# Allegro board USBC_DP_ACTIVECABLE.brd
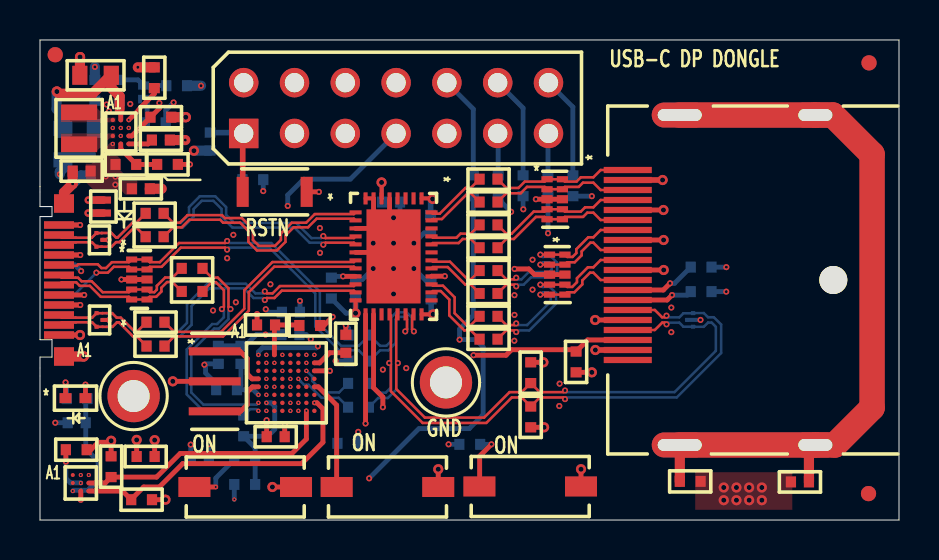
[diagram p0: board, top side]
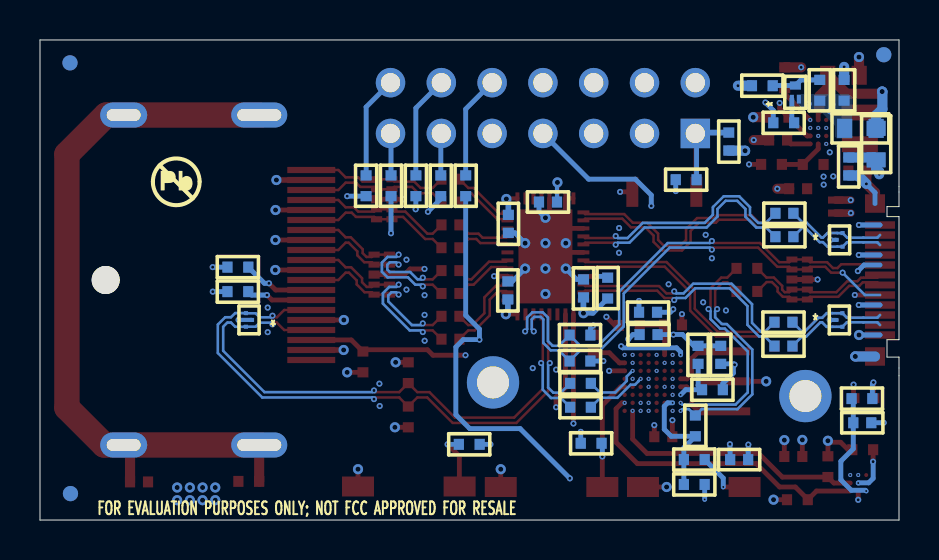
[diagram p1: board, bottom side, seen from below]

Outline 42.95 x 24 mm; copper layers: TOP, L2_GND, L3_SIG, L4_3P3V, L5_GND, BOTTOM. Coordinates in mm from the lower left corner of the outline.
Outline path: 0,24 0,15.67 0.6,15.67 0.6,15.17 0,15.17 0,9.02 0.6,9.02 0.6,8.15 0,8.15 0,0 42.95,0 42.95,24 0,24

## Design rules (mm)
net group DIFFPAIR0: nets DP_ML0N_ML3P DP_ML0P_ML3N
net group DIFFPAIR1: nets DP_ML1N_ML2P DP_ML1P_ML2N
net group DIFFPAIR2: nets DP_ML2N_ML1P DP_ML2P_ML1N
net group DIFFPAIR3: nets DP_ML3N_ML0P DP_ML3P_ML0N
net group DIFFPAIR4: nets N17413185 N17413188
net group DIFFPAIR5: nets N17413191 N17413194
net group DIFFPAIR6: nets N17413197 N17413200
net group DIFFPAIR7: nets N17413203 N17413206
net group DIFFPAIR8: nets DP_AUXN DP_AUXP
net group DIFFPAIR9: nets A10_RX2N_ML0N_ML3P A11_RX2P_ML0P_ML3N
net group DIFFPAIR10: nets N17415406 N17415415
net group DIFFPAIR11: nets A2_TX1P_ML2P_ML1N A3_TX1N_ML2N_ML1P
net group DIFFPAIR12: nets N17415496 N17415505
net group DIFFPAIR13: nets DM_USBC DP_USBC
net group DIFFPAIR14: nets B10_RX1N_ML3N_ML0P B11_RX1P_ML3P_ML0N
net group DIFFPAIR15: nets N17415457 N17415476
net group DIFFPAIR16: nets B2_TX2P_ML1P_ML2N B3_TX2N_ML1N_ML2P
net group DIFFPAIR17: nets N17415424 N17415436
net group DIFFPAIR18: nets USBC_SBU1_AUXP USBC_SBU2_AUXN
net group DIFFPAIR19: nets MSP_DPAUXN MSP_DPAUXP
net group DIFFPAIR20: nets DM_USBC_R DP_USBC_R

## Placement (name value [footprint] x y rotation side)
C1  220nF  [C0402]  5.78 8.7 180 top
C2  220nF  [C0402]  5.78 9.89 180 top
C3  100nF  [C0402]  19.56 11.48 270 bottom
C4  100nF  [C0402]  15.77 11.58 270 bottom
C5  220nF  [C0402]  22.43 17.04 180 top
C6  220nF  [C0402]  5.78 9.89 180 bottom
C7  220nF  [C0402]  22.43 15.9 180 top
C8  220nF  [C0402]  5.78 8.7 180 bottom
C9  220nF  [C0402]  22.43 14.76 180 top
C10  220nF  [C0402]  22.43 13.61 180 top
C11  220nF  [C0402]  22.43 12.47 180 top
C12  220pF  [C0402]  1.84 4.86 0 bottom
C13  220nF  [C0402]  5.73 14.17 180 bottom
C14  220nF  [C0402]  22.43 10.19 180 top
C15  220nF  [C0402]  22.43 11.33 180 top
C16  220nF  [C0402]  5.73 15.34 180 bottom
C17  4.7uF  [C0402]  2.51 17.68 270 bottom
C18  220nF  [C0402]  22.43 9.04 180 top
C19  1uF  [C0402]  38 1.91 180 top
C20  220nF  [C0402]  5.73 14.17 180 top
C21  220nF  [C0402]  5.73 15.33 180 top
C22  100nF  [C0402]  19.53 14.81 90 bottom
C23  100nF  [C0402]  17.55 15.9 180 bottom
C24  100nF  [C0402]  5.28 3.17 180 top
C25  220nF  [C0402]  7.99 3.02 180 bottom
C26  220nF  [C0402]  10.05 8.26 90 bottom
C27  1uF  [C0402]  8.92 8.26 90 bottom
C28  1nF  [C0402]  8.51 18.92 270 bottom
C29  100nF  [C0402]  11.79 4.17 180 top
C30  1uF  [C0402]  12.52 9.27 180 bottom
C31  100nF  [C0402]  12.55 10.39 180 bottom
C32  100nF  [C0402]  11.3 9.75 180 top
C33  470nF  [C0402]  15.29 8.81 90 top
C34  10uF  [C0603]  2.78 22.24 180 top
C35  10uF  [C0402]  5.04 16.57 0 top
C36  10uF  [C0402]  2.08 17.45 180 top
C37  1nF  [C0402]  6.05 19 180 top
D1  TPD1E05U06  [DPY0002AA]  1.78 6.09 0 top
D2  ESD114-U1-02EL  [SOD_882]  3.17 15.67 90 top
J1  Display_Port_Connector_Source  [CON_DP_SD-47272-001]  39.67 12 90 top
J2  DNI,HEADER 7X2  [HDR_THVT_2X7_100_M]  10.19 19.33 90 top
L1  1.5uH  [IND_DFE2016C]  1.96 19.58 270 top
LP1  DNI,LP_RED  [TP_THVT_060_RND]  4.68 6.2 0 top
LP2  DNI,LP_BLACK  [TP_THVT_060_RND]  20.3 6.88 0 top
NOREF  -  []  0 23.79 0 top
NOREF#2  -  []  42.72 0 90 top
NOREF#3  -  []  88.9 38.1 0 top
NOREF#4  -  []  -3.81 -69.85 0 top
NOREF#5  -  [unnamed#2]  41.43 1.32 0 top
NOREF#6  -  [unnamed#2]  0.76 23.27 0 top
NOREF#7  -  [unnamed#2]  41.45 22.86 0 top
NOREF#8  -  []  0 0 0 top
NOREF#9  -  [unnamed#2]  0.76 23.27 180 bottom
NOREF#10  -  []  36.11 16.94 180 bottom
NOREF#11  -  [unnamed#2]  41.45 22.86 180 bottom
NOREF#12  -  []  40.88 3.71 180 bottom
NOREF#13  -  [unnamed#2]  41.43 1.32 180 bottom
P1  Wurth 632712000021  [USB-C_SMRT_632_712_000_021]  0 12 90 top
Q1  TF412S  [SOT-883]  5.18 21.39 90 bottom
R1  1k  [R0402]  14.57 11.6 270 bottom
R2  0  [R0402]  1.85 6.07 180 bottom
R3  1M  [R0402]  32.51 1.93 0 top
R4  1M  [R0402]  26.8 7.9 270 top
R5  1M  [R0402]  33.06 12.64 0 bottom
R6  1M  [R0402]  33.06 11.42 0 bottom
R7  0  [R0402]  15.93 6.83 0 bottom
R8  0  [R0402]  15.93 5.64 0 bottom
R9  2M  [R0402]  15.95 7.95 180 bottom
R10  2M  [R0402]  15.95 9.25 180 bottom
R11  4.7M  [R0402]  24.54 7.37 90 top
R12  470k  [R0402]  24.54 5.16 270 top
R13  100k  [R0402]  3.96 21.49 90 bottom
R14  0  [R0402]  6.83 21.72 180 bottom
R15  806  [R0402]  5.77 19.86 0 bottom
R16  DNI,1k  [R0402]  2.74 21.49 90 bottom
R17  4.7k  [R0402]  5.08 1.02 180 top
R18  4.7k  [R0402]  3.56 2.67 270 top
R19  100k  [R0402]  1.81 3.52 180 top
R20  47k  [R0402]  10.64 17.02 180 bottom
R21  1.4k  [R0402]  10.18 4.71 90 bottom
R22  100  [R0402]  10.24 3.02 0 bottom
R23  1M  [R0402]  10.24 1.78 0 bottom
R24  0  [R0402]  9.33 6.52 0 bottom
R25  0  [R0402]  13.49 9.73 0 top
R26  0  [R0402]  26.64 16.71 270 bottom
R27  0  [R0402]  24.16 16.71 270 bottom
R28  DNI,0  [R0402]  22.91 16.71 270 bottom
R29  DNI,0  [R0402]  25.4 16.71 270 bottom
R30  DNI,100k  [R0402]  15.39 3.84 180 bottom
R31  DNI,100k  [R0402]  21.49 3.78 0 bottom
R32  DNI,0  [R0402]  21.67 16.71 90 bottom
R33  DNI,0  [R0603]  1.14 18.8 90 bottom
R34  0  [R0603]  1.93 19.58 180 bottom
R35  0  [R0402]  4.29 17.78 180 top
R36  1M  [R0402]  6.05 20.14 180 top
R37  DNI,100k  [R0402]  6.38 17.78 180 top
R38  100k  [R0402]  5.71 22.12 270 top
R39  27  [R0402]  7.6 12.58 0 top
R40  27  [R0402]  7.6 11.43 0 top
SW1  DIP_SPST  [SW_SMVT_CHS-01TA]  10.26 1.65 0 top
SW2  PushButton-SPST  [SW_SMVT_KXT]  11.73 16.41 180 top
SW3  DIP_SPST  [SW_SMVT_CHS-01TA]  17.37 1.65 0 top
SW4  DIP_SPST  [SW_SMVT_CHS-01TA]  24.51 1.68 0 top
U1  TUSB544  [RNQ0040A]  17.68 13.18 270 top
U2  TPD4E05U06  [DQA0010A]  4.97 12.03 0 top
U3  TUSB422IYFP  [YFP_BGA_9]  2.04 1.85 0 top
U4  MSP430F5528IYFF  [YFF0064A]  12.32 6.86 0 top
U5  TPS63051YFFT  [YFF0012A]  4.04 19.41 0 top
U6  TPD4E02B04  [DQA]  25.74 16.04 270 top
U7  TPD4E02B04  [DQA]  25.86 12.27 270 top
U8  ESD122  [DMX0003A]  2.97 14.01 180 top
U9  ESD122  [DMX0003A]  2.97 14.01 180 bottom
U10  ESD122  [DMX0003A]  2.98 10 180 bottom
U11  ESD122  [DMX0003A]  2.98 10 180 top
U12  ESD122  [DMX0003A]  32.5 10.01 0 bottom
Y1  4MHz  [XTAL_SM_3_CSTCR_G15L]  8.74 6.93 270 top

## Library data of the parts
C1 C2 C5-C16 C18 C20 C21 C37 = cc0402
C3 C4 C22-C24 = CAP NP
C17 C19 C25-C36 = CAP
D1 D2 = TPD1E05U06
J1 = Display_Port_Connector_Source_0
J2 = HEADER 7X2
L1 = INDUCTOR
LP1 LP2 = TESTLOOP
P1 = Type C Plug_0
Q1 = TF412S
R1 R2 R7 R8 R13-R16 R33-R35 R37 R38 = R
R3-R6 R9-R12 R17-R32 R36 R39 R40 = R_2
SW1-SW4 = SW MAG-SPST
U1 = TUSB1044RNQ
U2 = TPD4E05U06
U3 = TUSB422_WCSP
U4 = MSP430F5528IYFF_1
U5 = TPS63051YFFT
U6 U7 = TPD4E02B04
U8-U12 = ESD122
Y1 = XM/SM_0

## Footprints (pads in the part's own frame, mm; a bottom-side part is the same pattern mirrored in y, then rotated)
C0402
  rect 0.51x0.55 smd: 1(-0.45,0) 2(0.45,0)
C0603
  rect 0.76x0.95 smd: 1(-0.787,0) 2(0.787,0)
CON_DP_SD-47272-001
  round 1.4 hole 1.4 unplated: (0,0)
  rect 0.31x2.4 smd: 1(5.5,10.28) 2(5,10.28) 3(4.5,10.28) 4(4,10.28) 5(3.5,10.28) 6(3,10.28) 7(2.5,10.28) 8(2,10.28) 9(1.5,10.28) 10(1,10.28) 11(0.5,10.28) 12(0,10.28) 13(-0.5,10.28) 14(-1,10.28) 15(-1.5,10.28) 16(-2,10.28) 17(-2.5,10.28) 18(-3,10.28) 19(-3.5,10.28) 20(-4,10.28)
  oval 1.25x2.8 hole 0.6x2.2: 21(-8.25,7.68) 24(8.25,7.68)
  oval 1.25x2.35 hole 0.6x1.7: 22(-8.25,0.9) 23(8.25,0.9)
DMX0003A
  rect 0.2x0.2 smd: 1(-0.15,0) 2(0.15,-0.34) 3(0.15,0.34)
DPY0002AA
  rect 0.6x0.5 smd: 1(-0.5,0) 2(0.5,0)
DQA
  rect 0.305x0.559 smd: 1(-1,-0.385) 2(-0.5,-0.385) 4(0.5,-0.385) 5(1,-0.385) 6(1,0.385) 7(0.5,0.385) 9(-0.5,0.385) 10(-1,0.385)
  rect 0.406x0.559 smd: 3(0,-0.385) 8(0,0.385)
DQA0010A
  rect 0.55x0.3 smd: 1(-0.385,1) 2(-0.385,0.5) 4(-0.385,-0.5) 5(-0.385,-1) 6(0.385,-1) 7(0.385,-0.5) 9(0.385,0.5) 10(0.385,1)
  rect 0.55x0.4 smd: 3(-0.385,0) 8(0.385,0)
HDR_THVT_2X7_100_M
  rect 1.473x1.473 hole 0.965: 1(0,0)
  round 1.473 hole 0.965: 2(2.54,0) 3(0,-2.54) 4(2.54,-2.54) 5(0,-5.08) 6(2.54,-5.08) 7(0,-7.62) 8(2.54,-7.62) 9(0,-10.16) 10(2.54,-10.16) 11(0,-12.7) 12(2.54,-12.7) 13(0,-15.24) 14(2.54,-15.24)
IND_DFE2016C
  rect 0.787x1.803 smd: 1(-0.794,0) 2(0.794,0)
R0402
  rect 0.51x0.55 smd: 1(-0.52,0) 2(0.52,0)
R0603
  rect 0.76x0.95 smd: 1(-0.787,0) 2(0.787,0)
RNQ0040A
  rect 0.6x0.2 smd: 1(-2.9,1.4) 2(-2.9,1) 3(-2.9,0.6) 4(-2.9,0.2) 5(-2.9,-0.2) 6(-2.9,-0.6) 7(-2.9,-1) 8(-2.9,-1.4) 21(2.9,-1.4) 22(2.9,-1) 23(2.9,-0.6) 24(2.9,-0.2) 25(2.9,0.2) 26(2.9,0.6) 27(2.9,1) 28(2.9,1.4)
  rect 0.2x0.6 smd: 9(-2.2,-1.9) 10(-1.8,-1.9) 11(-1.4,-1.9) 12(-1,-1.9) 13(-0.6,-1.9) 14(-0.2,-1.9) 15(0.2,-1.9) 16(0.6,-1.9) 17(1,-1.9) 18(1.4,-1.9) 19(1.8,-1.9) 20(2.2,-1.9) 29(2.2,1.9) 30(1.8,1.9) 31(1.4,1.9) 32(1,1.9) 33(0.6,1.9) 34(0.2,1.9) 35(-0.2,1.9) 36(-0.6,1.9) 37(-1,1.9) 38(-1.4,1.9) 39(-1.8,1.9) 40(-2.2,1.9)
  rect 4.7x2.7 smd: 41(0,0)
SOD_882
  rect 0.356x0.762 smd: 1(-0.325,0) 2(0.325,0)
SOT-883
  rect 0.43x0.2 smd: 1(-0.34,0.175) 2(-0.34,-0.175)
  rect 0.41x0.55 smd: 3(0.34,0)
SW_SMVT_CHS-01TA
  rect 1.6x1 smd: 1(-2.54,0) 2(2.54,0)
SW_SMVT_KXT
  rect 0.6x1.5 smd: 1(-1.6,0) 2(1.6,0)
TP_THVT_060_RND
  round 2.616 hole 1.6: 1(0,0)
unnamed#2
  round 0.762 smd: (0,0)
USB-C_SMRT_632_712_000_021
  rect 0.35x1.5 smd: A1(-2.75,-0.95) A2(-2.25,-0.95) A3(-1.75,-0.95) A4(-1.25,-0.95) A5(-0.75,-0.95) A6(-0.25,-0.95) A7(0.25,-0.95) A8(0.75,-0.95) A9(1.25,-0.95) A10(1.75,-0.95) A11(2.25,-0.95) A12(2.75,-0.95) B1(2.75,-0.95) B2(2.25,-0.95) B3(1.75,-0.95) B4(1.25,-0.95) B5(0.75,-0.95) B8(-0.75,-0.95) B9(-1.25,-0.95) B10(-1.75,-0.95) B11(-2.25,-0.95) B12(-2.75,-0.95)
  rect 0.9x1 smd: C1(-3.825,-1.2) C2(3.825,-1.2) C3(-3.825,-1.2) C4(3.825,-1.2)
XTAL_SM_3_CSTCR_G15L
  rect 0.4x2.6 smd: 1(-1.5,0) 2(0,0) 3(1.5,0)
YFF0012A
  round 0.22 smd: A1(-0.4,0.6) A2(0,0.6) A3(0.4,0.6) B1(-0.4,0.2) B2(0,0.2) B3(0.4,0.2) C1(-0.4,-0.2) C2(0,-0.2) C3(0.4,-0.2) D1(-0.4,-0.6) D2(0,-0.6) D3(0.4,-0.6)
YFF0064A
  round 0.22 smd: A1(-1.4,1.4) A2(-1,1.4) A3(-0.6,1.4) A4(-0.2,1.4) A5(0.2,1.4) A6(0.6,1.4) A7(1,1.4) A8(1.4,1.4) B1(-1.4,1) B2(-1,1) B3(-0.6,1) B4(-0.2,1) B5(0.2,1) B6(0.6,1) B7(1,1) B8(1.4,1) C1(-1.4,0.6) C2(-1,0.6) C3(-0.6,0.6) C4(-0.2,0.6) C5(0.2,0.6) C6(0.6,0.6) C7(1,0.6) C8(1.4,0.6) D1(-1.4,0.2) D2(-1,0.2) D3(-0.6,0.2) D4(-0.2,0.2) D5(0.2,0.2) D6(0.6,0.2) D7(1,0.2) D8(1.4,0.2) E1(-1.4,-0.2) E2(-1,-0.2) E3(-0.6,-0.2) E4(-0.2,-0.2) E5(0.2,-0.2) E6(0.6,-0.2) E7(1,-0.2) E8(1.4,-0.2) F1(-1.4,-0.6) F2(-1,-0.6) F3(-0.6,-0.6) F4(-0.2,-0.6) F5(0.2,-0.6) F6(0.6,-0.6) F7(1,-0.6) F8(1.4,-0.6) G1(-1.4,-1) G2(-1,-1) G3(-0.6,-1) G4(-0.2,-1) G5(0.2,-1) G6(0.6,-1) G7(1,-1) G8(1.4,-1) H1(-1.4,-1.4) H2(-1,-1.4) H3(-0.6,-1.4) H4(-0.2,-1.4) H5(0.2,-1.4) H6(0.6,-1.4) H7(1,-1.4) H8(1.4,-1.4)
YFP_BGA_9
  round 0.2 smd: A1(-0.4,0.4) A2(0,0.4) A3(0.4,0.4) B1(-0.4,0) B2(0,0) B3(0.4,0) C1(-0.4,-0.4) C2(0,-0.4) C3(0.4,-0.4)

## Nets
GND: C3.1 C4.1 C12.1 C17.2(B) C19.2(B) C22.1 C23.1 C24.1 C25.2(B) C26.2(B) C27.2(B) C28.2(B) C29.2(B) C30.2(B) C31.2(B) C32.2(B) C33.2(B) C34.2(B) C35.2(B) C36.2(B) C37.1 D1.2(A) D2.2(A) J1.2(GND1) J1.5(GND2) J1.8(GND3) J1.11(GND4) J1.16(GND6) J1.19(RTN) J2.9 LP2.1 P1.A1(GND#A1) P1.A12(GND#A12) P1.B1(GND#B1) P1.B12(GND#B12) P1.C1(GND#C1) P1.C2(GND#C2) P1.C3(GND#C3) P1.C4(GND#C4) R3.2 R4.2 R5.2 R6.2 R9.2 R10.2 R11.2 R12.2 R15.2 R16.2 R23.1 R37.1 R38.1 SW2.1 SW3.2 SW4.2 U1.5(SWAP) U1.7(SLP_S0#) U1.8(DIR0) U1.11(DIR1) U1.14(VIO_SEL) U1.41(PAD/GND) U2.3(GND#3) U2.8(GND#8) U3.C2(GND) U4.A4(AVSS1) U4.A8(DVSS1) U4.D2(AVSS2) U4.H2(VSSU) U4.H6(DVSS2) U5.B1(GND) U5.C2(PFM/PWM) U6.3(GND#3) U6.8(GND#8) U7.3(GND#3) U7.8(GND#8) U8.1(GND) U9.1(GND) U10.1(GND) U11.1(GND) U12.1(GND) Y1.2(GND)
A2_TX1P_ML2P_ML1N: C1.2 P1.A2(SSTXP1) U11.3(IO2)
A3_TX1N_ML2N_ML1P: C2.2 P1.A3(SSTXN1) U11.2(IO1)
A10_RX2N_ML0N_ML3P: C20.2 P1.A10(SSRXN2) U8.3(IO2)
A11_RX2P_ML0P_ML3N: C21.2 P1.A11(SSRXP2) U8.2(IO1)
B2_TX2P_ML1P_ML2N: C16.2 P1.B2(SSTXP2) U9.3(IO2)
B3_TX2N_ML1N_ML2P: C13.2 P1.B3(SSTXN2) U9.2(IO1)
B10_RX1N_ML3N_ML0P: C6.2 P1.B10(SSRXN1) U10.3(IO2)
B11_RX1P_ML3P_ML0N: C8.2 P1.B11(SSRXP1) U10.2(IO1)
C_CC1: C12.2 R2.1 U3.C1(CC1)
DM_USBC: P1.A7(DN1) R39.1 U2.4(D2+) U2.7(NC7)
DM_USBC_R: R39.2 U4.G1(PU.1/DM)
DP_AUXN: J1.17(AUX_N) R8.2 R11.1 U1.25(AUXN) U12.3(IO2)
DP_AUXP: J1.15(AUX_P) R7.2 R12.1 U1.24(AUXP) U12.2(IO1)
DP_CAD: J1.13(CAD) R5.1
DP_ML0N_ML3P: C7.1 J1.3(ML_0N) U6.2(IO2) U6.9(NC9)
DP_ML0P_ML3N: C5.1 J1.1(ML_0P) U6.1(IO1) U6.10(NC10)
DP_ML1N_ML2P: C10.1 J1.6(ML_1N) U6.5(IO4) U6.6(NC6)
DP_ML1P_ML2N: C9.1 J1.4(ML_1P) U6.4(IO3) U6.7(NC7)
DP_ML2N_ML1P: C11.1 J1.9(ML_2N) U7.2(IO2) U7.9(NC9)
DP_ML2P_ML1N: C15.1 J1.7(ML_2P) U7.1(IO1) U7.10(NC10)
DP_ML3N_ML0P: C14.1 J1.12(ML_3N) U7.5(IO4) U7.6(NC6)
DP_ML3P_ML0N: C18.1 J1.10(ML_3P) U7.4(IO3) U7.7(NC7)
DP_USBC: P1.A6(DP1) R40.1 U2.5(D2-) U2.6(NC6)
DP_USBC_R: R21.2 R40.2 U4.H1(PU.0/DP)
DPTX_GND: C19.1(A) J1.21(GND7) J1.22(GND8) J1.23(GND9) J1.24(GND10) R3.1
HDMI_CEC: J1.14(GND5) R6.1
I2C_EN: R1.1 U1.17(I2C_EN)
MSP_3P3V: C24.2 C27.1(A) C29.1(A) C30.1(A) C31.1(A) J2.4 R17.1 R18.1 R19.1 R20.1 R24.1 R25.2 R30.1 R31.1 SW1.2 U3.A3(VDD) U4.A7(DVCC1) U4.H5(DVCC2)
MSP_422_SCL: R18.2 R29.2 U1.21(FLIP/SCL) U3.B3(SCL) U4.H7(P3.1/UCB0SOMI/UCB0SCL)
MSP_422_SDA: R17.2 R28.2 U1.22(CTL0/SDA) U3.C3(SDA) U4.G8(P3.0/UCB0SIMO/UCB0SDA)
MSP_422INTN: R19.2 R32.1 U3.B2(INT_N) U4.C8(P1.3/TA0.2)
MSP_CFG1: R31.2 SW4.1 U4.E5(P2.0/TA1.1)
MSP_CFG2: R30.2 SW3.1 U4.E8(P2.1/TA1.2)
MSP_DPAUXN: R8.1 U4.D6(P1.5/TA0.4)
MSP_DPAUXP: R7.1 U4.C7(P1.4/TA0.3)
MSP_HPDIN_OUT: J1.18(HPD) R4.1 U4.B7(P1.0/TA0CLK/ACLK)
MSP_INTN: J2.10 R32.2
MSP_PUR: R21.1 R22.2 R23.2 U4.G2(PUR)
MSP_RXD: R26.2 U4.G5(P3.4/UCA0RXD/UCA0SOMI)
MSP_RXD_R: J2.14 R26.1
MSP_SCL: J2.13 R29.1
MSP_SDA: J2.11 R28.1
MSP_TPS_PG: R36.2 U4.D7(P1.6/TA1CLK/CBOUT) U5.C3(PG)
MSP_TPSEN: R38.2 U4.B2(P6.4/CB4/A4) U5.A3(EN)
MSP_TPSLIM0: U4.B3(P6.5/CB5/A5) U5.B2(LIM0)
MSP_TPSLIM1: U4.A2(P6.6/CB6/A6) U5.B3(LIM1)
MSP_TUSB544_HPD: U1.32(HPDIN) U4.A1(P6.2/CB2/A2)
MSP_TXD: R27.2 U4.G6(P3.3/UCA0TXD/UCA0SIMO)
MSP_TXD_R: J2.12 R27.1
MSP_V18: C25.1(A) U4.E2(V18)
MSP_VUSB: C26.1(A) R24.2 U4.F1(VUSB)
MSP_WEAKEN_RA#: R14.1 U4.C4(P6.3/CB3/A3)
MSPAVCC1: C32.1(A) R25.1 U4.A3(AVCC1)
R_CC1: D1.1(K) P1.A5(CC1) R2.2
RST_SBWTDIO: C28.1(A) J2.1 R20.2 SW2.2 U4.D5(RST/NMI/SBWTDIO)
T2IN: U4.E1(P5.2/XT2IN) Y1.3
T2OUT: U4.D1(P5.3/XT2OUT) Y1.1
TEST_SBWTCK: J2.7 U4.E3(TEST/SBWTCK)
TPS_3P3V: C3.2 C4.2 C22.2 C23.2 C35.1(A) C36.1(A) R1.2 R35.2 R36.1 U1.1(VCC#1) U1.6(VCC#6) U1.20(VCC#20) U1.28(VCC#28) U5.D1(VOUT)
TPS_L1: L1.1 U5.A1(L1)
TPS_L2: L1.2 U5.C1(L2)
TPS_SS: C37.2 U5.D3(SS)
TPS_VIN: C34.1(A) R33.2 R34.2 U5.A2(VIN)
TPSFB: R35.1 R37.2 U5.D2(FB)
TYPEC_VBUS: C17.1(A) D2.1(K) LP1.1 P1.A4(VBUS#A4) P1.A9(VBUS#A9) P1.B4(VBUS#B4) P1.B9(VBUS#B9) R33.1 U3.A2(VBUSIN) U4.F2(VBUS)
USBC_SBU1_AUXP: P1.A8(SBU1) R10.1 U1.27(SBU1) U2.1(D1+) U2.10(NC10)
USBC_SBU2_AUXN: P1.B8(SBU2) R9.1 U1.26(SBU2) U2.2(D1-) U2.9(NC9)
VCONN: P1.B5(CC2) Q1.2(DRAIN) R13.1 R16.1 R34.1
N17347753: C33.1(A) U4.B8(VCORE)
N17354680: R22.1 SW1.1
N17413185: C5.2 U1.40(DRX2P)
N17413188: C7.2 U1.39(DRX2N)
N17413191: C9.2 U1.37(DTX2P)
N17413194: C10.2 U1.36(DTX2N)
N17413197: C11.2 U1.34(DTX1N)
N17413200: C15.2 U1.33(DTX1P)
N17413203: C14.2 U1.31(DRX1N)
N17413206: C18.2 U1.30(DRX1P)
N17415406: C21.1 U1.9(URX2P)
N17415415: C20.1 U1.10(URX2N)
N17415424: C16.1 U1.12(UTX2P)
N17415436: C13.1 U1.13(UTX2N)
N17415457: C8.1 U1.19(URX1P)
N17415476: C6.1 U1.18(URX1N)
N17415496: C2.1 U1.15(UTX1N)
N17415505: C1.1 U1.16(UTX1P)
N17425671: Q1.3(GATE) R13.2 R14.2
N17429646: Q1.1(SOURCE) R15.1

Pads without a net: J1 20; J2 2 3 5 6 8; U1 2 3 4 23 29 35 38; U3 A1 B1; U4 A5 A6 B1 B4 B5 B6 C1 C2 C3 C5 C6 D3 D4 D8 E4 E6 E7 F3 F4 F5 F6 F7 F8 G3 G4 G7 H3 H4 H8

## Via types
v1: diameter 0.203, hole 0.102, TOP to BOTTOM, 41 vias
v2: diameter 0.305, hole 0.152, TOP to BOTTOM, 115 vias
v3: diameter 0.508, hole 0.254, TOP to BOTTOM, 43 vias

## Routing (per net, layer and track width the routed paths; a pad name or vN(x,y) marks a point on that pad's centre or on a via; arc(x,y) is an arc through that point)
GND: length 85.4
  TOP w0.203: U1.7 U1.8 ; U8.1 v2(3.43,14.01) ; U11.1 v2(3.46,10)
  TOP w0.241: R12.2 v3(25.21,4.64) ; J1.8 v3(31.18,14) ; U7.8 U7.3 24.73,12.27 24.45,12.55 23.73,12.55 v2(23.73,12.56) ; R11.2 v3(25.17,7.89) ; J1.16 v3(27.76,10) ; v2(4.07,12.03) U2.3 U2.8 ; U1.7 16.68,14.54 ; 16.68,14.54 17.18,14.04 17.18,13.63 17.63,13.18 U1.41 17.48,13.38 16.91,13.38 16.87,13.34 16.45,13.34 16.41,13.38 U1.14 ; 16.68,14.54 16.63,14.58 U1.11 ; C29.2 v2(11.33,4.99) ; SW2.1 v2(13.94,16.41) ; R4.2 v3(27.59,7.38) ; v3(17.68,15.11) 17.48,15.31 U1.5 ; D1.2 v2(2.27,6.77) ; C32.2 v2(10.85,10.29) ; v2(24.79,16.04) U6.3 U6.8 ; C24.1 v3(5.73,3.99) ; SW3.2 v3(19.91,2.54) ; J1.5 v3(31.17,15.5) ; R37.1 v2(7.5,17.78) ; U3.C2 v2(2.04,1.01) ; C33.2 v2(15.29,9.73) ; J1.11 v3(31.19,12.5) ; SW4.2 v3(27.05,2.54) ; Y1.2 v3(6.64,6.93)
  TOP w0.254: P1.A12 v2(2.01,14.75) ; P1.A1 v3(2,9.25)
  TOP w0.279: J1.2 v3(31.13,17) ; J1.19 v3(27.77,8.5)
  TOP w0.381: D2.2 v2(2.42,16)
  TOP w0.508: P1.C1 v3(2.18,8.18) ; C35.2 v2(6.08,16.57) ; P1.C2 1.2,16.37 v2(1.63,16.81) C36.2 ; R38.1 v2(4.89,22.64) ; C37.1 v2(7.26,19) ; C34.2 v3(2,23.15)
  L2_GND w0.076: 19.43,19.33 J2.9 ; J2.9 20.35,18.41 ; J2.9 21.26,19.33 ; J2.9 20.35,20.24
  L2_GND w0.584: LP2.1 20.3,8.37 ; LP2.1 21.79,6.88 ; LP2.1 18.81,6.88 ; LP2.1 20.3,5.39
  L5_GND w0.076: 19.43,19.33 J2.9 ; J2.9 20.35,20.24 ; J2.9 20.35,18.41 ; J2.9 21.26,19.33
  L5_GND w0.584: LP2.1 21.79,6.88 ; LP2.1 20.3,8.37 ; LP2.1 18.81,6.88 ; LP2.1 20.3,5.39
  BOTTOM w0.203: U10.1 v2(3.46,10) ; U12.1 v2(33.03,10.01) ; U8.1 v2(3.43,14.01)
  BOTTOM w0.241: v2(1.63,16.81) 1.2,16.37 P1.C2 ; C22.1 19.21,14.36 v3(18.69,13.84) ; C3.1 19.34,11.93 v3(18.69,12.57) ; C30.2 v2(11.28,9.27) 11.27,9.28 10.83,9.28 10.25,8.71 C26.2 C27.2 ; v2(6.68,20.88) 6.29,20.48 R15.2 ; v3(17.68,15.11) 18,15.44 C23.1 ; R10.2 15.43,9.59 v2(15.29,9.73) ; R9.2 v2(14.78,7.95) ; R5.2 v2(34.32,12.64) ; v2(11.29,10.54) 11.44,10.39 C31.2 ; C4.1 16.12,12.03 v3(16.66,12.57) ; C25.2 v2(7.53,3.77) ; R6.2 v2(34.31,11.42) ; C12.1 v2(0.76,4.86) ; R23.1 v1(9.72,1.03)
  BOTTOM w0.254: P1.A12 v2(2.01,14.75) ; P1.A1 v3(2,9.25)
  BOTTOM w0.508: P1.C1 v3(2.18,8.18) ; C17.2 2.05,17.23 v2(1.63,16.81) ; R16.2 v2(2.74,22.66) ; C28.2 v3(7.7,18.47)
  vias: v1(3.64,19.61) v1(4.04,19.21) v1(11.32,7.06) v1(11.32,5.46) v1(12.12,8.26) v1(12.92,5.46) v1(13.72,8.26) v2(8.65,10.48) v2(9.36,13.09) v2(9.67,14.26) v2(9.79,10.89) v2(11.52,11.79) v2(14,14.6) v2(14,13.36) v2(17.14,7.52) v2(18.31,7.59) v2(23.72,11.24) v2(23.72,10.26) v2(23.72,8.96) v2(24.63,13.01) v2(24.63,11.52) v2(25.98,6.82) v2(25.97,5.7) v2(31.57,10.62) v2(31.57,9.39) v3(16.66,13.84) v3(17.68,13.84) v3(17.68,12.57) v3(17.68,11.3) v3(34.19,1.63) v3(34.19,0.99) v3(34.82,1.63) v3(34.82,0.99) v3(35.46,1.63) v3(35.46,0.99) v3(36.09,1.63) v3(36.09,0.99)
A2_TX1P_ML2P_ML1N: length 5.1
  TOP w0.127: C1.2 4.84,9.18 4.66,9.18 3.95,9.89 3.85,9.89 3.62,9.66 3.12,9.66 3.12,9.66 U11.3 2.6,9.89 1.78,9.89 1.78,9.89 1.08,9.89 P1.A2
A3_TX1N_ML2N_ML1P: length 5.1
  TOP w0.127: C2.2 4.84,9.41 4.75,9.41 4.04,10.12 3.84,10.12 3.61,10.35 3.12,10.35 3.12,10.34 U11.2 2.6,10.12 1.78,10.12 1.78,10.12 1.08,10.12 P1.A3
A10_RX2N_ML0N_ML3P: length 5.1
  TOP w0.127: C20.2 4.81,14.64 4.72,14.64 3.98,13.89 3.8,13.89 3.57,13.67 3.09,13.67 3.09,13.67 U8.3 2.6,13.89 1.78,13.89 1.78,13.89 1.08,13.89 P1.A10
A11_RX2P_ML0P_ML3N: length 5.1
  TOP w0.127: P1.A11 1.08,14.12 1.78,14.12 1.78,14.12 2.59,14.12 U8.2 3.09,14.35 3.09,14.35 3.57,14.35 3.8,14.12 3.88,14.12 4.62,14.86 4.81,14.86 C21.2
B2_TX2P_ML1P_ML2N: length 5.1
  BOTTOM w0.127: P1.B2 1.08,14.12 1.78,14.12 1.78,14.12 2.59,14.12 U9.3 3.09,14.35 3.09,14.35 3.57,14.35 3.8,14.12 3.87,14.12 4.62,14.87 4.81,14.87 C16.2
B3_TX2N_ML1N_ML2P: length 5.1
  BOTTOM w0.127: C13.2 4.81,14.64 4.71,14.64 3.97,13.89 3.8,13.89 3.57,13.67 3.09,13.67 3.09,13.67 U9.2 2.6,13.89 1.78,13.89 1.78,13.89 1.08,13.89 P1.B3
B10_RX1N_ML3N_ML0P: length 5.1
  BOTTOM w0.127: C6.2 4.84,9.41 4.73,9.41 4.02,10.11 3.84,10.11 3.61,10.35 3.32,10.35 3.32,10.34 U10.3 2.61,10.12 1.78,10.12 1.78,10.12 1.08,10.12 P1.B10
B11_RX1P_ML3P_ML0N: length 5.1
  BOTTOM w0.127: P1.B11 1.08,9.89 1.78,9.89 1.78,9.89 2.61,9.89 U10.2 3.32,9.66 3.32,9.66 3.62,9.66 3.84,9.88 3.93,9.88 4.63,9.18 4.84,9.18 C8.2
C_CC1: length 5.9
  BOTTOM w0.241: R2.1 2.29,5.99 C12.2 2.29,3.56 2.91,2.94 2.91,2.01 2.39,1.49 1.68,1.49 v1(1.64,1.45)
DM_USBC: length 7.2
  TOP w0.127: P1.A7 1.08,12.12 1.78,12.12 1.78,12.11 1.9,12.11 2.08,11.94 2.59,11.94 3.13,11.39 4.45,11.39 U2.4 U2.7 5.49,11.39 5.71,11.39 5.84,11.52 5.84,11.71 6.26,12.13 6.63,12.13 R39.1
DM_USBC_R: length 11.6
  TOP w0.127: R39.2 8.59,12.12 8.89,12.12 9.42,11.59 9.42,10.65 v2(9.53,10.55)
  BOTTOM w0.127: v2(9.53,10.55) 9.42,10.45 9.42,10.05 8.95,9.57 8.71,9.57 7.56,8.43 7.56,6.38 8.17,5.77 10.83,5.77 v1(10.92,5.86)
DP_AUXN: length 31.4
  TOP w0.127: U1.25 17.81,10.22 17.81,7.93 v2(17.89,7.85) 17.81,7.77 17.81,6.55 19.24,5.12 22.2,5.12 23.48,6.39 24.08,6.39 R11.1 24.99,6.39 26.17,6.39 v2(26.25,6.48) ; v2(31.33,9.79) 31.24,9.87 31.11,9.87 30.74,9.5 J1.17
  BOTTOM w0.127: R8.2 16.91,6.1 17.4,6.1 17.81,6.52 17.81,7.77 v2(17.89,7.85) ; v2(26.25,6.48) 26.33,6.39 31.73,6.39 33.79,8.46 33.79,9.66 33.58,9.87 33.4,9.87 33.19,9.66 32.75,9.66 32.75,9.66 U12.3 32.17,9.66 31.97,9.87 31.41,9.87 v2(31.33,9.79)
DP_AUXP: length 32.3
  TOP w0.127: v2(31.33,10.22) 31.25,10.14 31.11,10.14 30.74,10.5 J1.15 ; v2(26.25,6.05) 26.17,6.13 24.99,6.13 R12.1 24.08,6.13 23.59,6.13 22.32,4.85 19.13,4.85 17.55,6.44 17.55,7.77 v2(17.46,7.85) 17.55,7.93 17.55,10.22 U1.24
  BOTTOM w0.127: v2(26.25,6.05) 26.33,6.13 31.84,6.13 34.06,8.35 34.06,9.77 33.69,10.14 33.4,10.14 33.19,10.35 32.75,10.35 32.75,10.35 U12.2 32.64,10.34 32.17,10.34 31.97,10.13 31.41,10.13 v2(31.33,10.22) ; v2(17.46,7.85) 17.55,7.77 17.55,6.63 17.29,6.37 16.91,6.37 R7.2
DP_CAD: length 3.6
  TOP w0.241: J1.13 31.17,11.5 v2(31.5,11.84)
  BOTTOM w0.241: R5.1 31.73,11.84 v2(31.5,11.84)
DP_ML0N_ML3P: length 7.2
  TOP w0.127: J1.3 28.03,16.5 27.67,16.87 27.15,16.87 26.94,16.66 26.24,16.66 U6.9 U6.2 25.24,16.66 24.35,16.66 24.03,16.34 23.32,16.34 C7.1
DP_ML0P_ML3N: length 7.2
  TOP w0.127: J1.1 28.03,17.5 27.67,17.14 27.04,17.14 26.83,16.92 26.24,16.92 U6.10 U6.1 25.24,16.92 24.24,16.92 23.92,16.61 23.32,16.61 C5.1
DP_ML1N_ML2P: length 7.5
  TOP w0.127: J1.6 28.03,15 27.67,15.37 27.36,15.37 27.15,15.16 26.24,15.16 U6.6 U6.5 25.24,15.16 24.8,15.16 23.69,14.05 23.32,14.05 C10.1
DP_ML1P_ML2N: length 7.5
  TOP w0.127: J1.4 28.03,16 27.67,15.63 27.25,15.63 27.04,15.42 26.24,15.42 U6.7 U6.4 25.24,15.42 24.69,15.42 23.58,14.32 23.32,14.32 C9.1
DP_ML2N_ML1P: length 9.2
  TOP w0.127: v2(25.02,12.77) U7.2 U7.9 26.36,12.89 26.74,12.89 27.08,13.24 27.08,13.43 27.52,13.87 27.67,13.87 28.03,13.5 J1.9 ; C11.1 23.32,12.03 23.73,12.03 v2(23.81,12.12)
  BOTTOM w0.127: v2(25.02,12.77) 25.14,12.89 25.46,12.89 25.59,12.76 25.59,12.53 25.46,12.4 24.44,12.4 24.07,12.03 23.89,12.03 v2(23.81,12.12)
DP_ML2P_ML1N: length 10
  TOP w0.127: C15.1 23.32,11.77 23.73,11.77 v2(23.81,11.68) ; J1.7 28.03,14.5 27.67,14.14 27.41,14.14 26.82,13.54 26.82,13.35 26.63,13.15 26.36,13.15 U7.10 U7.1 v2(25.02,13.27)
  BOTTOM w0.127: v2(23.81,11.68) 23.89,11.77 24.18,11.77 24.55,12.13 25.57,12.13 25.85,12.42 25.85,12.87 25.57,13.15 25.14,13.15 v2(25.02,13.27)
DP_ML3N_ML0P: length 9.4
  TOP w0.127: C14.1 23.32,9.75 23.73,9.75 v2(23.81,9.83) ; J1.12 28.03,12 27.67,12.37 27.5,12.37 27.12,11.98 27.12,11.78 26.72,11.39 26.36,11.39 U7.6 U7.5 v2(25.02,11.27)
  BOTTOM w0.127: v2(25.02,11.27) 25.14,11.39 25.38,11.39 25.54,11.23 25.54,10.93 24.35,9.75 23.89,9.75 v2(23.81,9.83)
DP_ML3P_ML0N: length 10.3
  TOP w0.127: J1.10 28.03,13 27.67,12.63 27.39,12.63 26.85,12.09 26.85,11.89 26.61,11.65 26.36,11.65 U7.7 U7.4 v2(25.02,11.77) ; v2(23.81,9.4) 23.73,9.48 23.32,9.48 C18.1
  BOTTOM w0.127: v2(23.81,9.4) 23.89,9.48 24.46,9.48 25.8,10.82 25.8,11.34 25.49,11.65 25.14,11.65 v2(25.02,11.77)
DP_USBC: length 7.2
  TOP w0.127: P1.A6 1.08,11.89 1.81,11.89 1.99,11.71 2.49,11.71 3.04,11.16 4.45,11.16 U2.5 U2.6 5.35,11.04 5.48,11.16 5.81,11.16 6.07,11.42 6.07,11.61 6.35,11.9 6.62,11.9 R40.1
DP_USBC_R: length 11.8
  TOP w0.127: v2(9.09,10.55) 9.19,10.65 9.19,11.49 8.8,11.89 8.59,11.89 R40.2
  BOTTOM w0.127: v1(10.92,5.46) 10.83,5.54 10.5,5.54 R21.2 9.87,5.54 8.07,5.54 7.34,6.28 7.34,8.52 8.61,9.8 8.85,9.8 9.19,10.14 9.19,10.45 v2(9.09,10.55)
DPTX_GND: length 37.3
  TOP w0.508: C19.1 38.45,3.43 J1.22 ; J1.21 31.99,3.75 R3.1
  TOP w1.27: J1.21 J1.22 39.74,3.75 41.61,5.61 41.61,18.29 39.64,20.25 J1.23 J1.24
HDMI_CEC: length 3.3
  TOP w0.241: J1.14 31.36,11 v2(31.6,11.25)
  BOTTOM w0.241: R6.1 32.37,11.25 v2(31.6,11.25)
I2C_EN: length 1.2
  TOP w0.241: U1.17 v2(15.15,12.18)
  BOTTOM w0.241: R1.1 14.63,12.18 v2(15.15,12.18)
MSP_3P3V: length 15
  TOP w0.241: v2(14.63,10.16) 14.2,9.73 R25.2 ; C29.1 v2(12.24,4.74) ; R17.1 v3(6.27,1.02) ; C24.2 v3(4.83,4.01) ; R18.1 v3(3.56,3.96) 3.48,3.89 2.92,3.89 2.54,3.52 R19.1 ; SW1.2 v3(11.62,1.65)
  L4_3P3V w0.076: J2.4 13.64,21.87 ; J2.4 12.73,20.95 ; J2.4 12.73,22.78 ; J2.4 11.81,21.87
  BOTTOM w0.241: C27.1 8.26,7.81 v2(8.22,7.76) 8.28,7.7 8.28,7.35 8.81,6.82 R24.1 ; C30.1 13.31,9.27 v2(13.54,9.04) ; R31.1 v2(20.43,3.78) ; R30.1 v2(15.91,4.41) ; C31.1 v2(13,10.95) ; R20.1 v2(11.16,16.45)
  vias: v1(2.44,2.25) v1(12.52,5.46) v1(13.32,8.26)
MSP_422_SCL: length 41.5
  TOP w0.241: U3.B3 3.26,1.85 R18.2 5.83,2.15 7.01,3.33 12.6,3.33 13.32,4.05 v1(13.32,5.46) ; U1.21 v2(16.28,4.83)
  L3_SIG w0.076: v1(13.32,5.46) 13.95,4.83 v2(16.28,4.83) 16.94,4.16 21.65,4.16 23.35,5.87 23.35,12.92 24.78,14.34 v2(25.4,14.34)
  BOTTOM w0.241: R29.2 25.4,14.34 v2(25.4,14.34)
MSP_422_SDA: length 44.5
  TOP w0.241: U1.22 16.68,6.61 17.14,6.15 v2(17.14,5.64) ; U3.C3 4.13,1.45 R17.2 4.56,1.03 5.18,1.65 5.97,1.65 7.14,2.82 13.08,2.82 14.15,3.89 14.15,5.56 13.85,5.86 v1(13.72,5.86)
  L3_SIG w0.076: v2(23.56,15.41) 22.52,14.38 22.52,5.87 21.45,4.8 18.51,4.8 17.31,6 13.86,6 v1(13.72,5.86) 13.94,5.64 v2(17.14,5.64)
  BOTTOM w0.241: R28.2 22.91,16.06 v2(23.56,15.41)
MSP_422INTN: length 44.9
  TOP w0.241: U4.C8 v2(14.49,7.46) ; v2(1.3,2.92) 1.29,2.92 R19.2
  L3_SIG w0.076: v2(16.46,2.08) 4.19,2.08 3.36,2.92 v2(1.3,2.92) ; v2(14.49,7.46) 14.51,7.44 14.8,7.44 16.09,8.73 19.44,8.73 19.71,9 20.97,9 v2(20.98,9.02)
  BOTTOM w0.241: v2(16.46,2.08) 18.95,4.57 21.46,4.57 22.16,5.26 22.16,8.65 21.79,9.02 20.99,9.02 v2(20.98,9.02) 20.98,9.55 21.67,10.24 R32.1 ; v2(1.3,2.92) 1.3,2.08 1.52,1.86 2.03,1.86 v1(2.04,1.85)
MSP_CFG1: length 16.7
  TOP w0.241: v2(22.57,3.78) 21.98,3.19 21.98,1.69 SW4.1
  L3_SIG w0.076: v1(12.52,6.66) 12.52,6.3 12.25,6.03 12.25,5.31 12.75,4.81 12.75,4.06 14.1,2.7 15.95,2.7 16.34,3.08 21.87,3.08 v2(22.57,3.78)
  BOTTOM w0.241: R31.2 v2(22.57,3.78)
MSP_CFG2: length 6.3
  TOP w0.241: SW3.1 v2(14.83,3.17) 14.83,5.74 13.92,6.66 U4.E8
  BOTTOM w0.241: v2(14.83,3.17) 14.83,3.8 R30.2
MSP_DPAUXN: length 3.1
  BOTTOM w0.127: v1(12.92,7.06) 13.03,6.95 13.03,6.94 13.2,6.77 13.42,6.77 14.08,6.11 14.93,6.11 R8.1
MSP_DPAUXP: length 2.9
  BOTTOM w0.127: v1(13.32,7.46) 13.33,7.46 13.44,7.35 13.61,7.18 13.61,6.96 14.19,6.38 14.95,6.38 R7.1
MSP_HPDIN_OUT: length 17.5
  TOP w0.241: J1.18 29.39,9 27.38,9 R4.1 26.71,8.51 23.58,8.51 23.3,8.24 v2(21.68,8.24)
  L3_SIG w0.076: v1(13.32,7.86) 13.35,7.86 14.13,7.08 14.92,7.08 16.36,8.52 21.4,8.52 v2(21.68,8.24)
MSP_INTN: length 5.2
  BOTTOM w0.241: J2.10 21.67,20.55 R32.2
MSP_PUR: length 6
  BOTTOM w0.241: v1(11.32,5.86) 11.57,5.86 11.74,5.69 11.74,4.54 11.39,4.19 R21.1 10.76,3.61 R22.2 R23.2
MSP_RXD: length 27
  L3_SIG w0.076: v1(12.52,5.86) 13,6.34 17.34,6.34 18.58,5.1 21.25,5.1 22.07,5.92 22.07,15.21 23.31,16.45 26.56,16.45 26.81,16.19 v2(27.59,16.19)
  BOTTOM w0.241: R26.2 v2(27.59,16.19)
MSP_RXD_R: length 5.1
  BOTTOM w0.241: R26.1 26.64,20.65 J2.14
MSP_SCL: length 2.1
  BOTTOM w0.241: J2.13 25.4,19.3 R29.1
MSP_SDA: length 2.1
  BOTTOM w0.241: R28.1 22.91,19.3 J2.11
MSP_TPS_PG: length 25.7
  TOP w0.241: U5.C3 4.59,19.21 R36.2 5.97,20.59 v2(5.97,20.85)
  L3_SIG w0.076: v2(5.97,20.85) 8.18,23.06 10.82,23.06 11.43,22.45 11.43,18.69 12.98,17.14 12.98,13.36 13.56,12.78 13.56,10.29 12.98,9.7 12.98,7.42 13.32,7.08 v1(13.32,7.06)
MSP_TPSEN: length 18.5
  TOP w0.241: v1(4.44,20.01) 4.93,20.49 5.01,20.61 5.71,21.31 R38.2
  L3_SIG w0.076: v1(11.32,7.86) 11.32,7.86 11.59,8.13 11.59,9.13 11.6,9.14 11.6,9.27 11.9,9.57 11.9,14.1 9.66,16.33 8.11,16.33 v1(4.44,20.01)
MSP_TPSLIM0: length 15.9
  L3_SIG w0.076: v1(11.72,7.86) 11.72,7.86 11.4,7.54 10.9,7.54 10.27,8.17 10.27,11.26 8.06,13.47 8.06,15.59 v1(4.04,19.61)
MSP_TPSLIM1: length 14.2
  L3_SIG w0.076: v1(11.32,8.26) 11.32,8.37 10.51,9.18 10.51,11.38 8.4,13.49 8.4,15.65 v1(4.44,19.61)
MSP_TUSB544_HPD: length 13.1
  TOP w0.241: U1.32 19.59,12.19 v2(20.24,12.19)
  L3_SIG w0.076: v2(20.24,12.19) 20.45,11.99 20.45,10.34 19.09,8.99 14.19,8.99 v2(13.89,8.69)
  BOTTOM w0.241: v1(10.92,8.26) 10.92,8.4 11.13,8.61 13.82,8.61 v2(13.89,8.69)
MSP_TXD: length 22
  L3_SIG w0.076: v2(24.17,15.54) 22.95,14.32 22.95,5.86 21.58,4.5 17.18,4.5 16.35,5.32 13.83,5.32 13.3,5.86 v1(12.92,5.86)
  BOTTOM w0.241: v2(24.17,15.54) 24.16,15.55 R27.2
MSP_TXD_R: length 5.2
  BOTTOM w0.241: J2.12 24.16,20.6 R27.1
MSP_V18: length 5.3
  L3_SIG w0.076: v1(11.32,6.66) 11.32,6.65 10.54,6.65 8.46,4.57 v2(8.46,3.79)
  BOTTOM w0.241: C25.1 v2(8.46,3.79)
MSP_VUSB: length 2.5
  BOTTOM w0.241: C26.1 10.05,6.71 R24.2 10.66,6.52 v1(10.92,6.26)
MSP_WEAKEN_RA#: length 16.9
  L3_SIG w0.076: v2(8.05,21.72) 8.53,21.23 8.53,17.83 12.12,14.25 12.12,9.44 11.85,9.18 11.85,8.15 12.12,7.88 v1(12.12,7.46)
  BOTTOM w0.508: v2(8.05,21.72) R14.1
MSPAVCC1: length 2.7
  TOP w0.241: U4.A3 11.72,9.72 C32.1 12.94,9.75 R25.1
R_CC1: length 7.9
  TOP w0.241: P1.A5 v2(2.21,11.25) ; D1.1 v2(1.28,6.88)
  L3_SIG w0.076: v2(1.28,6.88) 1.34,10.81 1.79,11.25 v2(2.21,11.25)
  BOTTOM w0.241: v2(1.28,6.88) 1.33,6.81 R2.2
RST_SBWTDIO: length 20.9
  TOP w0.279: J2.1 10.13,19.28 SW2.2
  L3_SIG w0.076: v1(12.52,7.06) 12.7,7.24 12.7,9.78 13.36,10.44 13.36,12.5 12.7,13.15 12.7,16 10.24,18.47 10.24,19.28 J2.1
  BOTTOM w0.241: J2.1 10.12,19.27 R20.2
  BOTTOM w0.279: C28.1 10.14,19.37 J2.1
T2IN: length 3.1
  TOP w0.241: U4.E1 10.62,6.66 10.36,6.4 10.36,5.77 10.03,5.43 Y1.3
T2OUT: length 3.2
  TOP w0.241: U4.D1 10.6,7.06 10.36,7.3 10.36,8.08 10.01,8.43 Y1.1
TEST_SBWTCK: length 16.6
  L3_SIG w0.076: v2(12.39,15.71) 12.39,7.33 11.72,6.66 v1(11.72,6.66)
  BOTTOM w0.241: v2(12.39,15.71) 12.39,16.25 13.18,17.04 15.52,17.04 J2.7
TPS_3P3V: length 8.2
  TOP w0.203: U1.6 v3(17.08,16.88) ; U1.1 19.6,16.08 v3(19.63,16.05) ; U1.20 v3(15.78,10.34) ; U1.28 19.66,10.28 v3(19.66,10.29)
  TOP w0.508: R36.1 v3(7.29,20.14)
  BOTTOM w0.203: v3(17.08,16.88) 17.1,16.86 C23.2
  BOTTOM w0.241: v3(15.78,10.34) 15.3,10.34 14.57,11.08 R1.2
  BOTTOM w0.279: v3(15.78,10.34) 15.78,11.13 C4.2 ; v3(19.66,10.29) 19.56,10.39 C3.2 ; v3(19.63,16.05) 19.53,15.95 C22.2
  vias: v1(3.64,18.81) v2(3.29,17.18) v2(3.46,18.39) v2(3.77,17.17) v2(3.77,16.77)
TPS_SS: length 1.2
  TOP w0.241: U5.D3 5.4,18.81 C37.2
TPS_VIN: length 7.6
  TOP w0.241: U5.A2 4.04,20.5 3.98,20.56
  TOP w0.508: 3.98,20.56 3.98,21.2 3.57,21.61 C34.1 3.54,22.24 2.62,21.32 0.95,21.32 v3(0.84,21.42)
  BOTTOM w0.241: R34.2 R33.2
  BOTTOM w0.508: R34.2 1.14,20.24 0.83,20.55 0.83,21.41 v3(0.84,21.42)
TPSFB: length 2.4
  TOP w0.241: R37.2 5.85,17.78 R35.1 4.04,18.55 U5.D2
TYPEC_VBUS: length 11.7
  TOP w0.254: v2(2.01,13.25) P1.A9 ; P1.A4 v2(2.01,10.75)
  TOP w0.381: D2.1 v2(2.41,15.35)
  L4_3P3V w0.584: LP1.1 6.17,6.2 ; LP1.1 4.68,7.68 ; LP1.1 3.19,6.2
  BOTTOM w0.254: P1.A9 v2(2.01,13.25) ; v2(2.01,10.75) P1.A4
  BOTTOM w0.508: v2(0.99,17.29) 0.99,17.41 1.14,17.57 R33.1 1.26,18.13 C17.1
  vias: v1(2.04,2.25) v1(11.32,6.26)
USBC_SBU1_AUXP: length 25.2
  TOP w0.127: U1.27 18.61,10.21 18.61,9.52 v2(18.69,9.43) ; v2(9.36,13.95) 9.26,13.85 6.95,13.85 5.99,12.89 5.49,12.89 U2.10 U2.1 4.45,12.89 3.59,12.89 3.3,12.6 3.08,12.6 2.89,12.79 1.92,12.79 1.84,12.71 0.99,12.71 P1.A8
  BOTTOM w0.127: v2(9.36,13.95) 9.46,13.85 11.56,13.85 13.99,11.42 13.99,9.77 15.05,8.71 15.94,8.71 R10.1 17,8.71 17.32,8.71 17.55,8.95 17.55,10.13 17.81,10.39 18.33,10.39 18.59,10.13 18.59,9.53 v2(18.69,9.43)
USBC_SBU2_AUXN: length 25.1
  TOP w0.127: U1.26 18.35,10.21 18.35,9.52 v2(18.26,9.43) ; v2(9.36,13.52) 9.26,13.62 7.04,13.62 6.08,12.66 5.49,12.66 U2.9 U2.2 4.45,12.66 3.69,12.66 3.4,12.37 v2(2.82,12.37)
  BOTTOM w0.127: v2(2.82,12.37) 1.7,11.25 P1.B8 ; v2(18.26,9.43) 18.36,9.53 18.36,10.03 18.24,10.16 17.91,10.16 17.78,10.03 17.78,8.85 17.42,8.48 17,8.48 R9.1 15.94,8.48 14.96,8.48 13.76,9.68 13.76,11.33 11.47,13.62 9.46,13.62 v2(9.36,13.52)
VCONN: length 1.2
  BOTTOM w0.241: P1.B5 1.75,12.75 v2(2.06,12.45)
  vias: v2(3.33,20.78) v2(3.45,20.44) v2(4.51,20.81)
N17347753: length 1.8
  TOP w0.241: C33.1 14.49,8.36 13.98,7.86 U4.B8
N17354680: length 2.8
  TOP w0.241: SW1.1 v1(8.79,1.65)
  BOTTOM w0.241: v1(8.79,1.65) 8.79,2.09 R22.1
N17413185: length 3.1
  TOP w0.127: U1.40 19.64,15.32 19.98,15.32 21.27,16.61 21.54,16.61 C5.2
N17413188: length 3.1
  TOP w0.127: U1.39 19.64,15.05 20.09,15.05 21.38,16.34 21.54,16.34 C7.2
N17413191: length 2.7
  TOP w0.127: U1.37 19.64,14.12 20.82,14.12 21.03,14.32 21.54,14.32 C9.2
N17413194: length 2.7
  TOP w0.127: U1.36 19.65,13.85 20.93,13.85 21.14,14.05 21.54,14.05 C10.2
N17413197: length 3
  TOP w0.127: C11.2 21.54,12.03 21.38,12.03 20.5,12.92 19.64,12.92 U1.34
N17413200: length 3
  TOP w0.127: C15.2 21.54,11.77 21.27,11.77 20.39,12.65 19.65,12.65 U1.33
N17413203: length 3.9
  TOP w0.127: U1.31 19.64,11.72 20.15,11.72 20.73,11.13 20.73,10.34 21.33,9.75 21.54,9.75 C14.2
N17413206: length 3.9
  TOP w0.127: C18.2 21.54,9.48 21.22,9.48 20.47,10.23 20.47,11.02 20.04,11.45 19.65,11.45 U1.30
N17415406: length 11.8
  TOP w0.127: C21.1 6.65,14.86 6.99,14.86 7.37,15.25 9.1,15.25 9.25,15.1 10.1,15.1 10.65,14.55 10.65,14 10.94,13.71 11.75,13.71 12.04,14 12.04,14.32 12.59,14.86 13.31,14.86 13.74,15.3 15.69,15.3 U1.9
N17415415: length 11.8
  TOP w0.127: U1.10 15.69,15.07 13.83,15.07 13.4,14.64 12.68,14.64 12.27,14.23 12.27,13.91 11.84,13.48 10.85,13.48 10.42,13.91 10.42,14.45 10,14.87 9.15,14.87 9.01,15.02 7.47,15.02 7.09,14.64 6.65,14.64 C20.1
N17415424: length 11.8
  TOP w0.127: v2(14.17,14.2) 14.27,14.1 15.69,14.1 U1.12
  BOTTOM w0.127: v2(14.17,14.2) 14.06,14.1 13.57,14.1 12.81,14.86 9.71,14.86 9.31,15.26 9.31,15.65 8.76,16.19 7.99,16.19 7.45,15.65 7.45,15.26 7.04,14.86 6.66,14.86 C16.1
N17415436: length 11.8
  TOP w0.127: U1.13 15.69,13.87 14.27,13.87 v2(14.17,13.77)
  BOTTOM w0.127: v2(14.17,13.77) 14.06,13.87 13.48,13.87 12.72,14.63 9.62,14.63 9.08,15.17 9.08,15.55 8.67,15.96 8.09,15.96 7.68,15.55 7.68,15.17 7.14,14.63 6.64,14.63 C13.1
N17415457: length 11.8
  TOP w0.127: U1.19 15.69,11.47 12.09,11.47 11.72,11.1 11.34,11.1 v2(11.24,11)
  BOTTOM w0.127: v2(11.24,11) 11.14,11.1 10.68,11.1 10.19,11.58 8.46,11.58 7.58,10.7 7.58,9.76 7,9.18 6.71,9.18 C8.1
N17415476: length 11.8
  TOP w0.127: U1.18 15.69,11.7 11.99,11.7 11.63,11.33 11.34,11.33 v2(11.24,11.43)
  BOTTOM w0.127: v2(11.24,11.43) 11.14,11.33 10.77,11.33 10.29,11.81 8.37,11.81 7.35,10.79 7.35,9.85 6.9,9.41 6.71,9.41 C6.1
N17415496: length 11.8
  TOP w0.127: C2.1 6.71,9.41 9.06,9.41 10.21,10.56 10.21,11.49 11.62,12.9 15.69,12.9 U1.15
N17415505: length 11.8
  TOP w0.127: C1.1 6.71,9.18 9.15,9.18 10.44,10.47 10.44,11.4 11.71,12.67 15.69,12.67 U1.16
N17425671: length 2.5
  BOTTOM w0.241: R13.2 4.9,22.01 Q1.3 6.3,21.73 R14.2
N17429646: length 1.2
  BOTTOM w0.241: Q1.1 5.36,19.97 R15.1

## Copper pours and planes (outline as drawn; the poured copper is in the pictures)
GND on TOP: 32.77,0.51 32.77,2.39 37.62,2.39 37.62,0.51
GND on L2_GND: 18.54,0.51 0.51,0.51 0.51,9.92 1.7,9.92 1.7,10.07 0.51,10.07 0.51,11.92 1.7,11.92 1.7,12.06 0.51,12.06 0.51,13.92 1.7,13.92 1.7,14.07 0.51,14.07 0.51,23.49 42.44,23.49 42.44,0.51 18.57,0.51
GND on L5_GND: 18.54,0.51 0.51,0.51 0.51,23.49 42.44,23.49 42.44,0.51 18.57,0.51
MSP_3P3V on L4_3P3V: 2.31,0.38 2.31,4.14 2.06,4.39 2.06,5.18 2.87,5.18 3.53,4.52 11.46,4.52 12.01,5.08 12.01,6.63 11.48,7.16 7.84,7.16 7.84,11.23 13.94,11.23 16.43,8.74 21.26,8.74 21.26,17.91 21.03,18.14 15.37,18.14 13.26,16.03 11.1,16.03 10.29,16.84 10.29,23.5 42.5,23.5 42.5,0.38
TPS_3P3V on TOP: 3.75,18.9 3.55,18.9 3.17,18.53 3.17,18.42 2.57,17.81 2.29,17.81 2.29,16.89 2.66,16.52 4.02,16.52 4.26,16.28 4.85,16.28 4.86,16.28 4.86,16.95 4.59,17.22 4.29,17.22 4.01,17.5 4.01,18.04 4.01,18.05 4.01,18.06 3.75,18.33
TPS_3P3V on L4_3P3V: 9.17,23.55 9.17,16.61 10.64,15.14 13.74,15.14 16.1,17.5 20.47,17.5 20.52,17.45 20.52,9.45 16.28,9.45 13.92,11.81 8.36,11.81 3.15,17.02 3.15,23.55
TPS_L1 on TOP: 1.04,20.78 2.66,20.78 3.33,20.12 3.77,20.12 3.77,19.89 1.06,19.89 1.04,19.91
TPS_L2 on TOP: 1.05,18.4 2.79,18.4 3.47,19.09 3.76,19.09 3.76,19.33 1.07,19.33 1.05,19.32
TYPEC_VBUS on L4_3P3V: 0.89,2.01 0.89,7.77 0.98,7.77 0.98,9.4 0.89,9.4 0.89,14.79 0.98,14.79 0.98,16.05 0.71,16.05 0.71,18.36 2.51,18.36 2.51,16.61 7.17,11.96 7.17,6.88 11.2,6.88 11.58,6.5 11.58,5.77 10.67,4.85 3.91,4.85 3.23,5.54 1.91,5.54 1.78,5.41 1.78,3.94 2.13,3.58 2.13,2.03 2.11,2.01
VCONN on BOTTOM: 5.11,21.29 2.49,21.29 2.34,21.13 2.34,19.08 3.1,19.08 3.2,19.18 3.2,19.71 4.01,20.52 4.78,20.52 5.11,20.85
VCONN on L3_SIG: 1.78,12.19 2.31,12.19 3.28,13.16 3.28,19.76 4.04,20.52 4.83,20.52 5.16,20.85 5.16,21.26 2.51,21.26 1.57,20.32 1.57,12.4

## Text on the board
BOTTOM: LAYER 6 - BOTTOM SIDE
Board Geometry/Soldermask Bottom: SOLDERMASK BOTTOM
Package Geometry/Pastemask Bottom: PASTEMASK BOTTOM
Ref Des/Silkscreen Bottom: FOR EVALUATION PURPOSES ONLY; NOT FCC APPROVED FOR RESALE | SILKSCREEN BOTTOM
TOP: LAYER 1 - TOP SIDE
Board Geometry/Soldermask Top: SOLDERMASK TOP
Package Geometry/Pastemask Top: PASTEMASK TOP
Ref Des/Silkscreen Top: RSTN | GND | USB-C DP DONGLE | SILKSCREEN TOP
L2_GND: LAYER 2 - GND PLANE
L3_SIG: LAYER 3 - SIG
L4_3P3V: LAYER 4 - 3P3V
L5_GND: LAYER 5 - GND PLANE
XSECTION_CHART: * AIR 0 MIL | * SOLDERMASK-0.8MIL 0.8 MIL | L1: COPPER_1/2OZ_PLATED 1.4 MIL | * CORE_0.150 5.91 MIL | L2: COPPER_1.0OZ 1.4 MIL | * FILL_0.05 1.97 MIL | L3: COPPER_1.0OZ 1.4 MIL | * CORE_0.05 1.97 MIL | L4: COPPER_1.0OZ 1.4 MIL | L5: COPPER_1.0OZ 1.4 MIL | L6: COPPER_1/2OZ_PLATED 1.4 MIL | DESIGN CROSS SECTION CHART | ___________________________ | TOTAL THICKNESS 27.73 MIL | 1-6
PAGE_OUTLINE: 134751
DIMENSION: FABRICATION DRAWING | CAD ORIGIN
User.6: LAYER 3 | LAYER 2 | LAYER 4 | LAYER 5 | LAYER 1 | LAYER 6 | LAYER | NO. | TABLE 1: | L3_SIG | L2_GND | L4_3P3v | L5_GND | TOP | BOTTOM | NAME | DIFFIRENTIAL PAIR | IMPEDANCE (OHMS) | 100 +/- 10% | 90 +/- 10% | DIFF TRACE | WIDTH | 0.005" | SPACING | 0.0055" | 0.004" | SINGLE ENDED | 50 +/- 10% | TRACE WIDTH | 0.003" | 0.0095" | REFERENCE | SPECIAL FAB NOTES: | PLACE DRILL CHART HERE: | 1:FAB SHOP MUST FOLLOW THE SOLDER MASK REVIEW LAYERS. | 2: | MIN. ANNULAR RING 2 MIL EXTERNAL PER IPC-6012C CLASS 2 | REGISTRATION TOLERANCES: METAL +/- X MIL,HOLES +/- X MIL | IMPEDANCE CONTROL: | BOARD SIZE (REFER ALSO ARRAY/PANEL PROFILING INFORMATION) | MIXED DIELECTRIC: | LAMINATE MATERIAL: | THICKNESS: | TOLERANCE: | COPPER THICKNESS (FINISHED): | BOARD FINISH: | NUMBER OF LAYERS: | MIN. TRACK WIDTH: | MIN. CLEARANCE  : | MIN. VIA PAD/DRILL: | THIEVING ALLOWED: | X | OUTER: | INNER SIGNAL: | INNER PLANE: | OTHER: | SILKSCREEN: | SOLDERMASK: (PER IPC-6011,6012) | BOARD SURFACE TREATMENT: | ADDITIONAL REQUIREMENTS: | VENDOR MARKING: | SILKSCREEN COLOR: | SOLDERMASK COLOR: | THROUGH-HOLE VIA TREATMENT: | VIA FILL USING NON-CONDUCTIVE EPOXY: | FOR WIRE BONDING: | VENDOR DATE CODE,UL,LOGO: | FR-4 HIGH Tg | 0.062" +/-10% | IPC-6012C TYPE 3 CLASS 2 | OTHER +/- | MICRO-SECTION | CERTIFICATES OF COMPLIANCE | NICKEL/GOLD (ENIG) | IMMERSION TIN | HARD GOLD | IN AN OPEN AREA | 1/4 OZ. | OPEN | NO | 6 | 5.0 MIL | 4.0 MIL | 12/06 MIL | NONE | DESIGN INFORMATION | ROGERS 4350B | 0.093" +/-10% | YES | TDR REPORTS/COUPONS | WHITE | GREEN | SOFT GOLD | TENTED | 1/2 OZ. | BOW & TWIST: | ORGANIC (OSP) | OTHER | WHERE INDICATED (SEE DRAWING) | YES - SEE TABLE 1 | ETCH | IDENTIFIER: | BLUE | RoHS | 1.0 OZ. | SILKSCREEN | PER SUPPLIED ARTWORK | ALL x MIL VIAS | 0.028" +/-.002 | ELECTRICAL TEST | UL 94V-0 | HASL | 2.0 OZ. | BREAK-AWAY | ENEPIG
User.10: FIGURE | SIZE | 4.0 | 6.0 | 10.0 | 38.0 | 63.0 | 55.12 | 66.93x23.62 | 86.61x23.62 | DRILL CHART: TOP to BOTTOM | ALL UNITS ARE IN MILS | TOLERANCE | +3.0/-4.0 | +3.0/-6.0 | +3.0/-10.0 | +3.0/-3.0 | +1.97/-19.69 | +1.97/-1.97 | PLATED | NON-PLATED | QTY | 41 | 115 | 43 | 14 | 2 | 1
